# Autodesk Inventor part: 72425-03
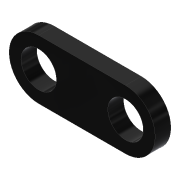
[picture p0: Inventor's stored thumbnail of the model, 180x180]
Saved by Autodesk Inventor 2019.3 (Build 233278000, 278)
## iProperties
Created: 2013-06
Part Number: 72425-03
Material: Ogólny
Document SubType Name: Modeling
Designer: CADENGINEERING4
Density: 1 g/cm^3
Appearance: Gładki — czarny
Author: CADENGINEERING4
Revision Number: ÈÎºÎ
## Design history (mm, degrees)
feature "ÊäÈë1"
node "Bryła1"
